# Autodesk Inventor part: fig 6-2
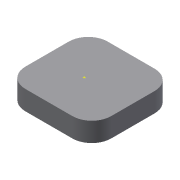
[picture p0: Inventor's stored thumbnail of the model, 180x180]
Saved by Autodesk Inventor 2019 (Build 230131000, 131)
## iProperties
Created: 2004-05
Part Number: fig 6-2
Document SubType Name: Modeling
Designer: CADCIM Technologies
Manufacturer: Standard
Standards Organization: Custom
Density: 1 g/cm^3
Material: Generic
Appearance: Default
Author: CADCIM Technologies
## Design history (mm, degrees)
sketch "Sketch1"
  geometry: L1 (0, 0)-(44.293, 0); L2 (44.293, 0)-(44.293, 42.442); L3 (44.293, 42.442)-(0, 42.442); L4 (0, 42.442)-(0, 0)
  constraints: 8 end point, 2 parallel, 1 horizontal, 1 perpendicular
extrude "Extrusion1" new body sketch "Sketch1" distance "d0" = 10; taper "d1" = 0 deg
fillet "Fillet1" dims "d2" = 10
sketch "Sketch2"
  geometry: 1 further point
sketch "Sketch3"
  geometry: L1 (10, 42.442)-(34.293, 42.442) reference; L2 (0, 10)-(0, 32.442) reference; L3 (34.293, 0)-(10, 0) reference; L4 (44.293, 32.442)-(44.293, 10) reference; A1 r 10 centre (34.293, 32.442) between (44.293, 32.442) and (34.293, 42.442) reference; A2 r 10 centre (10, 32.442) between (10, 42.442) and (0, 32.442) reference; A3 r 10 centre (10, 10) between (0, 10) and (10, 0) reference; A4 r 10 centre (34.293, 10) between (34.293, 0) and (44.293, 10) reference; 1 further point
workpoint "Work Point1"
body "Solid1"
